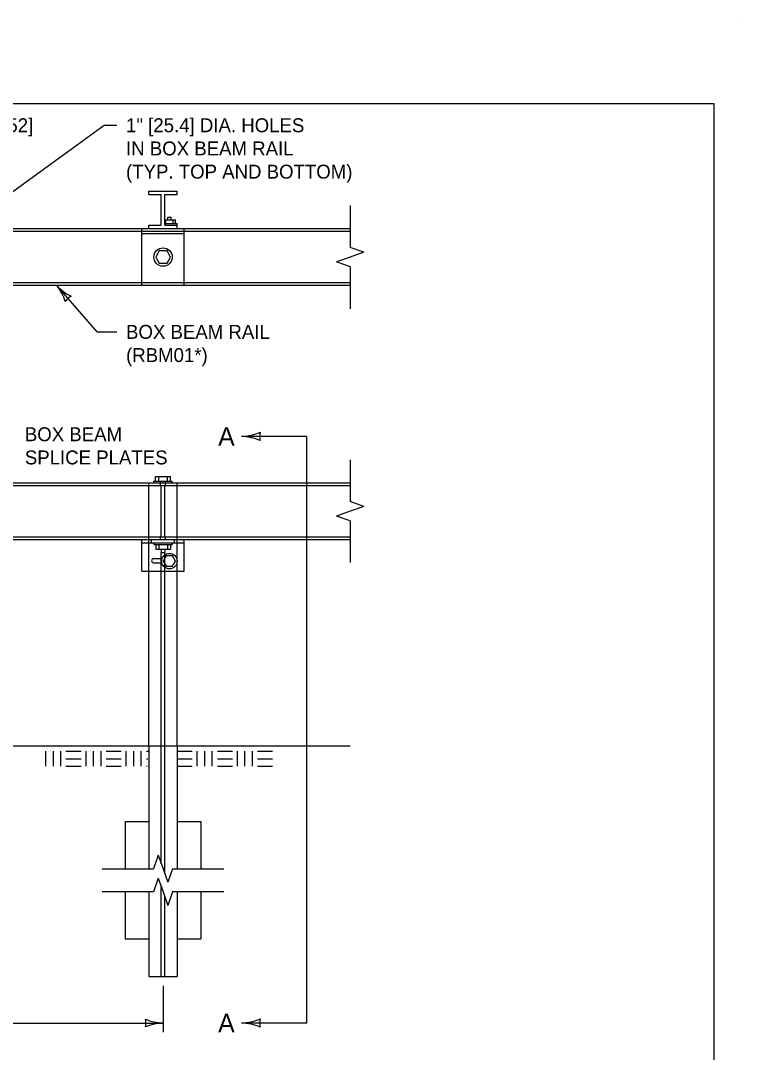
# Model space of a CAD drawing. Extents: x 49991.4 to 50021, y 49987.6 to 50011.4.
# Drawn here: x 50017.948 to 50021.038, y 50004.076 to 50008.524 of the extents above; entities that cross this region are included whole.
import ezdxf

# ---------------------------------------------------------------- set-up
doc = ezdxf.new("R2010")
doc.units = 0
for name, color, linetype in [('Level 1', 7, 'Continuous'), ('Level 2', 7, 'Continuous'), ('Level 3', 7, 'Continuous'), ('Level 4', 7, 'Continuous'), ('Level 6', 7, 'Continuous')]:
    doc.layers.add(name, color=color, linetype=linetype)

msp = doc.modelspace()

# ---------------------------------------------------------------- linework, layer by layer
at = {"layer": 'Level 1'}
for p, q in [((50021.0378, 50008.5236), (50021.0378, 50008.5236)), ((50018.5006, 50007.7742), (50018.5006, 50007.7888)), ((50018.5006, 50007.7888), (50018.6225, 50007.7888)), ((50018.5006, 50007.7742), (50018.5536, 50007.7742)), ((50018.5536, 50007.6422), (50018.5536, 50007.7742)), ((50018.5694, 50007.6422), (50018.5694, 50007.7742)), ((50018.5694, 50007.7742), (50018.6225, 50007.7742)), ((50018.6225, 50007.7742), (50018.6225, 50007.7888)), ((50018.5006, 50007.6422), (50018.5536, 50007.6422)), ((50018.5006, 50007.6264), (50018.5006, 50007.6422)), ((50018.5694, 50007.6649), (50018.6158, 50007.6649)), ((50018.5694, 50007.6485), (50018.6222, 50007.6485)), ((50018.5694, 50007.6422), (50018.6225, 50007.6422)), ((50018.5734, 50007.6485), (50018.5734, 50007.6649)), ((50018.6049, 50007.6485), (50018.6049, 50007.6649)), ((50018.6158, 50007.6485), (50018.6158, 50007.6649)), ((50018.6222, 50007.6422), (50018.6222, 50007.6485)), ((50018.6225, 50007.6264), (50018.6225, 50007.6422)), ((50019.3683, 50007.6264), (50017.1193, 50007.6264)), ((50019.3683, 50007.3818), (50017.1193, 50007.3818)), ((50017.121, 50006.5309), (50019.3683, 50006.5309)), ((50018.5214, 50006.5384), (50018.6012, 50006.5384)), ((50018.5214, 50006.5309), (50018.5214, 50006.5384)), ((50018.5297, 50006.5384), (50018.5297, 50006.5581)), ((50018.5297, 50006.5581), (50018.5936, 50006.5581)), ((50018.5427, 50006.5384), (50018.5427, 50006.5581)), ((50018.5805, 50006.5384), (50018.5805, 50006.5581)), ((50018.5936, 50006.5384), (50018.5936, 50006.5581)), ((50018.6012, 50006.5309), (50018.6012, 50006.5384)), ((50017.121, 50006.287), (50019.3683, 50006.287)), ((50018.4699, 50006.1508), (50018.4699, 50006.287)), ((50018.4699, 50006.2724), (50018.6528, 50006.2724)), ((50018.5215, 50006.2724), (50018.5215, 50006.2649)), ((50018.5215, 50006.2649), (50018.6013, 50006.2649)), ((50018.5298, 50006.2649), (50018.5298, 50006.2452)), ((50018.5428, 50006.2649), (50018.5428, 50006.2452)), ((50018.5806, 50006.2649), (50018.5806, 50006.2452)), ((50018.5937, 50006.2649), (50018.5937, 50006.2452)), ((50018.6013, 50006.2724), (50018.6013, 50006.2649)), ((50018.6528, 50006.1508), (50018.6528, 50006.287)), ((50018.5298, 50006.2452), (50018.5937, 50006.2452)), ((50018.5203, 50006.2045), (50018.5575, 50006.2045)), ((50018.5203, 50006.1859), (50018.5566, 50006.1859)), ((50018.4699, 50006.1508), (50018.6528, 50006.1508)), ((50018.5004, 50005.3957), (50018.5004, 50006.1508)), ((50018.6223, 50005.3957), (50018.6223, 50006.1508)), ((50019.3683, 50005.3957), (50015.2686, 50005.3957)), ((50018.0562, 50005.3091), (50018.0562, 50005.3741)), ((50018.0887, 50005.3091), (50018.0887, 50005.3741)), ((50018.1212, 50005.3091), (50018.1212, 50005.3741)), ((50018.1429, 50005.3741), (50018.2079, 50005.3741)), ((50018.2296, 50005.3091), (50018.2296, 50005.3741)), ((50018.2621, 50005.3091), (50018.2621, 50005.3741)), ((50018.2946, 50005.3091), (50018.2946, 50005.3741)), ((50018.3162, 50005.3741), (50018.3813, 50005.3741)), ((50018.403, 50005.3091), (50018.403, 50005.3741)), ((50018.4354, 50005.3091), (50018.4354, 50005.3741)), ((50018.4679, 50005.3091), (50018.4679, 50005.3741)), ((50018.6223, 50005.3741), (50018.6223, 50005.3741)), ((50018.6223, 50005.3741), (50018.6873, 50005.3741)), ((50018.709, 50005.3091), (50018.709, 50005.3741)), ((50018.7415, 50005.3091), (50018.7415, 50005.3741)), ((50018.774, 50005.3091), (50018.774, 50005.3741)), ((50018.7957, 50005.3741), (50018.8606, 50005.3741)), ((50018.8823, 50005.3091), (50018.8823, 50005.3741)), ((50018.9149, 50005.3091), (50018.9149, 50005.3741)), ((50018.9474, 50005.3091), (50018.9474, 50005.3741)), ((50018.969, 50005.3741), (50019.034, 50005.3741)), ((50018.1429, 50005.3416), (50018.2079, 50005.3416)), ((50018.3162, 50005.3416), (50018.3813, 50005.3416)), ((50018.6223, 50005.3416), (50018.6873, 50005.3416)), ((50018.7957, 50005.3416), (50018.8606, 50005.3416)), ((50018.969, 50005.3416), (50019.034, 50005.3416)), ((50018.1429, 50005.3091), (50018.2079, 50005.3091)), ((50018.3162, 50005.3091), (50018.3813, 50005.3091)), ((50018.6223, 50005.3091), (50018.6873, 50005.3091)), ((50018.7957, 50005.3091), (50018.8606, 50005.3091)), ((50018.969, 50005.3091), (50019.034, 50005.3091))]:
    msp.add_line(p, q, dxfattribs=at)
for points in [[(50020.9378, 50008.1646), (50009.7374, 50008.1646), (50009.7374, 49999.8856), (50020.9378, 49999.8856)], [(50018.5451, 50007.4777), (50018.5786, 50007.4777), (50018.5933, 50007.5044), (50018.5786, 50007.5311), (50018.5451, 50007.5311), (50018.5305, 50007.5044)], [(50018.5749, 50006.1713), (50018.603, 50006.1713), (50018.6153, 50006.1936), (50018.603, 50006.2161), (50018.5749, 50006.2161), (50018.5626, 50006.1936)]]:
    msp.add_lwpolyline(points, close=True, dxfattribs=at)
for points in [[(50018.5818, 50007.6649), (50018.5818, 50007.6767)], [(50018.5818, 50007.6767), (50018.5959, 50007.6767)], [(50018.5959, 50007.6649), (50018.5959, 50007.6767)], [(50018.5529, 50006.2452), (50018.5529, 50006.231)], [(50018.5529, 50006.231), (50018.5698, 50006.231)], [(50018.5698, 50006.2452), (50018.5698, 50006.231)], [(50018.4896, 50005.3741), (50018.4985, 50005.3741)], [(50018.5004, 50005.3957), (50018.5004, 50005.3957)], [(50018.6223, 50005.3957), (50018.6223, 50005.3957)], [(50018.4896, 50005.3416), (50018.4954, 50005.3416)], [(50018.4896, 50005.3091), (50018.4924, 50005.3091)]]:
    msp.add_lwpolyline(points, dxfattribs=at)
for centre, radius in [((50018.5615, 50007.5043), 0.0395), ((50018.589, 50006.1936), 0.0333)]:
    msp.add_circle(centre, radius, dxfattribs=at)
msp.add_arc((50018.5217, 50006.1952), 0.00938, 98.5498, 261.4502, dxfattribs=at)
at = {"layer": 'Level 3'}
for points in [[(50017.5707, 50007.5391), (50018.3072, 50008.0726)], [(50018.3072, 50008.0726), (50018.362, 50008.0726)], [(50018.2768, 50007.1818), (50018.1029, 50007.3818)], [(50018.2768, 50007.1818), (50018.362, 50007.1818)], [(50018.5614, 50004.3622), (50018.5614, 50004.1622)], [(50015.6364, 50004.2022), (50018.5614, 50004.2022)]]:
    msp.add_lwpolyline(points, dxfattribs=at)
for centre, radius, start, end in [((50017.9293, 50007.243), 0.2223, 18.463, 38.6465), ((50018.271, 50007.5432), 0.233, 223.8343, 243.0841), ((50018.187, 50007.285), 0.0548, 113.1458, 148.8681), ((50018.5705, 50004.4243), 0.2223, 247.456, 267.6395), ((50018.4332, 50004.2022), 0.0548, 342.1388, 17.8612), ((50018.5729, 50003.9695), 0.233, 92.8273, 112.0772)]:
    msp.add_arc(centre, radius, start, end, dxfattribs=at)
at = {"layer": 'Level 4'}
for p, q in [((50019.3683, 50007.615), (50017.1193, 50007.615)), ((50018.4699, 50007.3818), (50018.4699, 50007.6264)), ((50018.47, 50007.6053), (50018.6528, 50007.6053)), ((50018.6528, 50007.3818), (50018.6528, 50007.6264)), ((50019.3683, 50007.3932), (50017.1193, 50007.3932)), ((50018.5004, 50006.1508), (50018.5004, 50006.5309)), ((50018.55, 50006.5198), (50018.55, 50006.5384)), ((50018.5726, 50006.5198), (50018.5726, 50006.5384)), ((50018.6222, 50006.1508), (50018.6222, 50006.5309)), ((50017.121, 50006.5198), (50019.3683, 50006.5198)), ((50018.5529, 50006.2981), (50018.5529, 50006.5198)), ((50018.5698, 50006.2981), (50018.5698, 50006.5198)), ((50017.121, 50006.2981), (50019.3683, 50006.2981)), ((50018.5123, 50006.2724), (50018.5123, 50006.287)), ((50018.55, 50006.287), (50018.55, 50006.2981)), ((50018.5726, 50006.287), (50018.5726, 50006.2981)), ((50018.611, 50006.2724), (50018.611, 50006.287)), ((50018.5538, 50004.889), (50018.5538, 50006.231)), ((50018.569, 50004.8461), (50018.569, 50006.231)), ((50018.5004, 50005.3957), (50018.5004, 50004.8676)), ((50018.6223, 50005.3957), (50018.6223, 50004.8676)), ((50018.3989, 50005.0708), (50018.5004, 50005.0708)), ((50018.3989, 50005.0708), (50018.3989, 50004.8676)), ((50018.6223, 50005.0708), (50018.7238, 50005.0708)), ((50018.7238, 50005.0708), (50018.7238, 50004.8676)), ((50018.3989, 50004.7678), (50018.3989, 50004.5647)), ((50018.5004, 50004.7678), (50018.5004, 50004.4022)), ((50018.5538, 50004.4022), (50018.5538, 50004.7893)), ((50018.569, 50004.4022), (50018.569, 50004.7464)), ((50018.6223, 50004.7678), (50018.6223, 50004.4022)), ((50018.7238, 50004.7678), (50018.7238, 50004.5647)), ((50018.3989, 50004.5647), (50018.5004, 50004.5647)), ((50018.6223, 50004.5647), (50018.7238, 50004.5647)), ((50018.5004, 50004.4022), (50018.6223, 50004.4022))]:
    msp.add_line(p, q, dxfattribs=at)
at = {"layer": 'Level 6'}
for p, q in [((50019.3683, 50007.7264), (50019.3683, 50007.5456)), ((50019.3683, 50007.5042), (50019.3098, 50007.4834)), ((50019.4268, 50007.5249), (50019.3683, 50007.5456)), ((50019.4268, 50007.5249), (50019.3683, 50007.5042)), ((50019.3683, 50007.4627), (50019.3098, 50007.4834)), ((50019.3683, 50007.4627), (50019.3683, 50007.2818)), ((50019.3683, 50006.6309), (50019.3683, 50006.4501)), ((50019.4268, 50006.4293), (50019.3683, 50006.4501)), ((50019.3683, 50006.4086), (50019.3098, 50006.3879)), ((50019.4268, 50006.4293), (50019.3683, 50006.4086)), ((50019.3683, 50006.3672), (50019.3098, 50006.3879)), ((50019.3683, 50006.3672), (50019.3683, 50006.187)), ((50018.5406, 50004.9261), (50018.5199, 50004.8676)), ((50018.5406, 50004.9261), (50018.5614, 50004.8676)), ((50018.2989, 50004.8676), (50018.5199, 50004.8676)), ((50018.5614, 50004.8676), (50018.5821, 50004.8091)), ((50018.6028, 50004.8676), (50018.5821, 50004.8091)), ((50018.6028, 50004.8676), (50018.8238, 50004.8676)), ((50018.5406, 50004.8263), (50018.5199, 50004.7678)), ((50018.5406, 50004.8263), (50018.5614, 50004.7678)), ((50018.5199, 50004.7678), (50018.2989, 50004.7678)), ((50018.5614, 50004.7678), (50018.5821, 50004.7093)), ((50018.6028, 50004.7678), (50018.5821, 50004.7093)), ((50018.8238, 50004.7678), (50018.6028, 50004.7678))]:
    msp.add_line(p, q, dxfattribs=at)
for points in [[(50019.1797, 50006.7309), (50018.8997, 50006.7309)], [(50019.1797, 50006.7309), (50019.1797, 50004.2022)], [(50019.1797, 50004.2022), (50018.8997, 50004.2022)]]:
    msp.add_lwpolyline(points, dxfattribs=at)
for centre, radius, start, end in [((50018.8874, 50006.9791), 0.2485, 272.8273, 292.0772), ((50019.0365, 50006.7309), 0.0584, 162.1388, 197.8612), ((50018.8899, 50006.494), 0.2371, 67.456, 87.6395), ((50018.8874, 50004.4504), 0.2485, 272.8273, 292.0772), ((50019.0365, 50004.2022), 0.0584, 162.1388, 197.8612), ((50018.8899, 50003.9653), 0.2371, 67.456, 87.6395)]:
    msp.add_arc(centre, radius, start, end, dxfattribs=at)

# ---------------------------------------------------------------- texts
at = {"layer": 'Level 2'}
msp.add_text('6" [152]', height=0.06, rotation=360, dxfattribs=at).set_placement((50017.728, 50008.0426))
for s, height, p in [('1" [25.4] DIA. HOLES', 0.06, (50018.402, 50008.0426)), ('IN BOX BEAM RAIL ', 0.06, (50018.402, 50007.9426)), ('(TYP. TOP AND BOTTOM)', 0.06, (50018.402, 50007.8426)), ('BOX BEAM RAIL', 0.06, (50018.402, 50007.1518)), ('(RBM01*)', 0.06, (50018.402, 50007.0518)), ('BOX BEAM', 0.06, (50017.9657, 50006.7105)), ('A', 0.08, (50018.7992, 50006.6909)), ('SPLICE PLATES', 0.06, (50017.9657, 50006.6105)), ('A', 0.08, (50018.7992, 50004.1622))]:
    msp.add_text(s, height=height, dxfattribs=at).set_placement(p)

doc.saveas('drawing.dxf')
